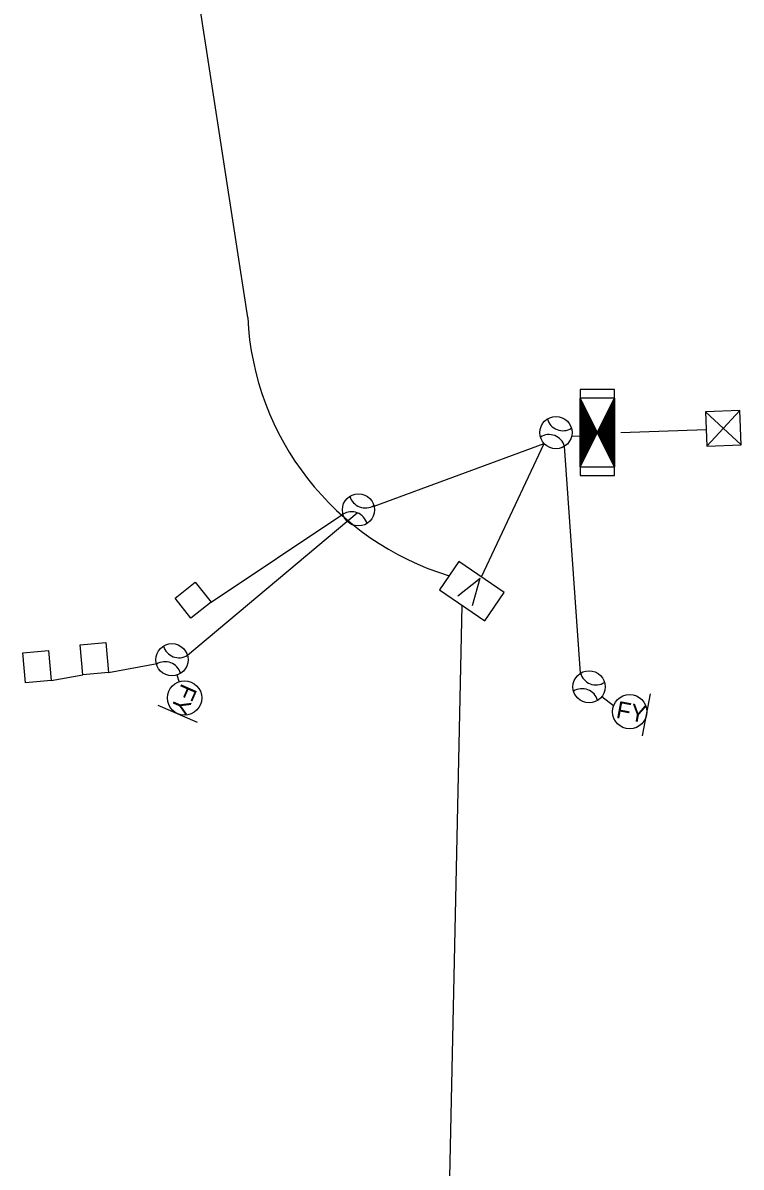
# Model space of a CAD drawing. Extents: x 601562 to 605316, y 332050 to 402250.
# Drawn here: x 604324.3 to 604491.7, y 339332.4 to 339598.9 of the extents above; entities that cross this region are included whole.
import ezdxf

# ---------------------------------------------------------------- set-up
doc = ezdxf.new("R2010")
doc.units = 0
doc.layers.add('P_FTMS', color=7, linetype='Continuous')
doc.layers.add('P_FTMSConduit', color=7, linetype='Continuous')

# ---------------------------------------------------------------- blocks, each defined once
blk = doc.blocks.new('FTMS_FCV')
at = {"layer": 'P_FTMS'}
blk.add_line((12.7, 16.3), (0.6, -21.9), dxfattribs=at)
blk.add_lwpolyline([(39.1, 24.4), (-39.1, 24.4), (-39.1, -24.4), (39.1, -24.4)], close=True, dxfattribs=at)
blk.add_lwpolyline([(-12.1, 16.2), (0.6, -21.9)], dxfattribs=at)
blk = doc.blocks.new('FTMS_FCB')
at = {"layer": 'P_FTMS'}
for p, q in [((-48.3, 24.1), (-48, 24.4)), ((-45.5, 22.7), (-47.1, 24.4)), ((-46.9, 23.4), (-46, 24.4)), ((-45.5, 22.8), (-43.9, 24.4)), ((-41.4, 20.7), (-45.1, 24.4)), ((-44.1, 22.1), (-41.8, 24.4)), ((-37.2, 18.6), (-43, 24.4)), ((-42.8, 21.4), (-39.8, 24.4)), ((-41.4, 20.7), (-37.7, 24.4)), ((-33.1, 16.5), (-40.9, 24.4)), ((-40, 20), (-35.6, 24.4)), ((-29, 14.5), (-38.9, 24.4)), ((-38.6, 19.3), (-33.6, 24.4)), ((-37.2, 18.6), (-31.5, 24.4)), ((-24.8, 12.4), (-36.8, 24.4)), ((-35.9, 17.9), (-29.4, 24.4)), ((-20.7, 10.3), (-34.7, 24.4)), ((-34.5, 17.2), (-27.3, 24.4)), ((-33.1, 16.5), (-25.3, 24.4)), ((-16.5, 8.3), (-32.7, 24.4)), ((-31.7, 15.9), (-23.2, 24.4)), ((-12.4, 6.2), (-30.6, 24.4)), ((-30.3, 15.2), (-21.1, 24.4)), ((-29, 14.5), (-19.1, 24.4)), ((-8.3, 4.1), (-28.5, 24.4)), ((-27.6, 13.8), (-17, 24.4)), ((-4.1, 2.1), (-26.4, 24.4)), ((-26.2, 13.1), (-14.9, 24.4)), ((-24.8, 12.4), (-12.9, 24.4)), ((0, 0), (-24.4, 24.4)), ((-23.5, 11.7), (-10.8, 24.4)), ((1.4, 0.7), (-22.3, 24.4)), ((-22.1, 11), (-8.7, 24.4)), ((-20.7, 10.3), (-6.7, 24.4)), ((2.8, 1.4), (-20.2, 24.4)), ((-19.3, 9.7), (-4.6, 24.4)), ((4.1, 2.1), (-18.2, 24.4)), ((-17.9, 9), (-2.5, 24.4)), ((-16.6, 8.3), (-0.4, 24.4)), ((5.5, 2.8), (-16.1, 24.4)), ((-15.2, 7.6), (1.6, 24.4)), ((6.9, 3.4), (-14, 24.4)), ((-13.8, 6.9), (3.7, 24.4)), ((-12.4, 6.2), (5.8, 24.4)), ((8.3, 4.1), (-12, 24.4)), ((-11, 5.5), (7.8, 24.4)), ((9.7, 4.8), (-9.9, 24.4)), ((-9.7, 4.8), (9.9, 24.4)), ((-8.3, 4.1), (12, 24.4)), ((11, 5.5), (-7.8, 24.4)), ((-6.9, 3.4), (14, 24.4)), ((12.4, 6.2), (-5.8, 24.4)), ((-5.5, 2.8), (16.1, 24.4)), ((-4.1, 2.1), (18.2, 24.4)), ((13.8, 6.9), (-3.7, 24.4)), ((-2.8, 1.4), (20.2, 24.4)), ((15.2, 7.6), (-1.6, 24.4)), ((-1.4, 0.7), (22.3, 24.4)), ((0, 0), (24.4, 24.4)), ((16.6, 8.3), (0.4, 24.4)), ((17.9, 9), (2.5, 24.4)), ((4.1, 2.1), (26.5, 24.4)), ((19.3, 9.7), (4.6, 24.4)), ((20.7, 10.3), (6.7, 24.4)), ((8.3, 4.1), (28.5, 24.4)), ((22.1, 11), (8.7, 24.4)), ((23.4, 11.7), (10.8, 24.4)), ((12.4, 6.2), (30.6, 24.4)), ((24.8, 12.4), (12.9, 24.4)), ((26.2, 13.1), (14.9, 24.4)), ((16.6, 8.3), (32.7, 24.4)), ((27.6, 13.8), (17, 24.4)), ((29, 14.5), (19.1, 24.4)), ((20.7, 10.3), (34.7, 24.4)), ((30.3, 15.2), (21.1, 24.4)), ((31.7, 15.9), (23.2, 24.4)), ((24.8, 12.4), (36.8, 24.4)), ((33.1, 16.6), (25.3, 24.4)), ((34.5, 17.2), (27.3, 24.4)), ((29, 14.5), (38.9, 24.4)), ((35.9, 17.9), (29.4, 24.4)), ((37.2, 18.6), (31.5, 24.4)), ((33.1, 16.6), (40.9, 24.4)), ((38.6, 19.3), (33.5, 24.4)), ((40, 20), (35.6, 24.4)), ((37.2, 18.6), (43, 24.4)), ((41.4, 20.7), (37.7, 24.4)), ((42.8, 21.4), (39.8, 24.4)), ((41.4, 20.7), (45.1, 24.4)), ((44.1, 22.1), (41.8, 24.4)), ((45.5, 22.8), (43.9, 24.4)), ((45.5, 22.8), (47.1, 24.4)), ((46.9, 23.5), (46, 24.4)), ((48.3, 24.1), (48, 24.4)), ((-24.4, -24.4), (0, 0)), ((24.4, -24.4), (0, 0)), ((-38.9, -24.4), (-29, -14.5)), ((-36.8, -24.4), (-24.8, -12.4)), ((-34.8, -24.4), (-20.7, -10.4)), ((-32.7, -24.4), (-16.6, -8.3)), ((-23.2, -24.4), (-31.7, -15.9)), ((-30.6, -24.4), (-12.4, -6.2)), ((-21.1, -24.4), (-30.3, -15.2)), ((-19, -24.4), (-29, -14.5)), ((-28.5, -24.4), (-8.3, -4.1)), ((-17, -24.4), (-27.6, -13.8)), ((-26.5, -24.4), (-4.1, -2.1)), ((-14.9, -24.4), (-26.2, -13.1)), ((-12.8, -24.4), (-24.8, -12.4)), ((-10.8, -24.4), (-23.4, -11.7)), ((-22.3, -24.4), (1.4, -0.7)), ((-8.7, -24.4), (-22.1, -11)), ((-6.6, -24.4), (-20.7, -10.3)), ((-20.3, -24.4), (2.8, -1.4)), ((-4.6, -24.4), (-19.3, -9.7)), ((-18.2, -24.4), (4.1, -2.1)), ((-2.5, -24.4), (-17.9, -9)), ((-0.4, -24.4), (-16.6, -8.3)), ((-16.1, -24.4), (5.5, -2.8)), ((1.6, -24.4), (-15.2, -7.6)), ((-14.1, -24.4), (6.9, -3.4)), ((3.7, -24.4), (-13.8, -6.9)), ((5.8, -24.4), (-12.4, -6.2)), ((-12, -24.4), (8.3, -4.1)), ((7.8, -24.4), (-11, -5.5)), ((-9.9, -24.4), (9.7, -4.8)), ((9.9, -24.4), (-9.7, -4.8)), ((12, -24.4), (-8.3, -4.1)), ((-7.8, -24.4), (11, -5.5)), ((14.1, -24.4), (-6.9, -3.5)), ((-5.8, -24.4), (12.4, -6.2)), ((16.1, -24.4), (-5.5, -2.8)), ((18.2, -24.4), (-4.1, -2.1)), ((-3.7, -24.4), (13.8, -6.9)), ((20.3, -24.4), (-2.8, -1.4)), ((-1.6, -24.4), (15.2, -7.6)), ((22.3, -24.4), (-1.4, -0.7)), ((0.4, -24.4), (16.6, -8.3)), ((2.5, -24.4), (17.9, -9)), ((26.5, -24.4), (4.1, -2.1)), ((4.6, -24.4), (19.3, -9.7)), ((6.6, -24.4), (20.7, -10.3)), ((28.5, -24.4), (8.3, -4.1)), ((8.7, -24.4), (22.1, -11)), ((10.8, -24.4), (23.4, -11.7)), ((30.6, -24.4), (12.4, -6.2)), ((12.8, -24.4), (24.8, -12.4)), ((14.9, -24.4), (26.2, -13.1)), ((32.7, -24.4), (16.6, -8.3)), ((17, -24.4), (27.6, -13.8)), ((19.1, -24.4), (29, -14.5)), ((34.7, -24.4), (20.7, -10.3)), ((21.1, -24.4), (30.3, -15.2)), ((23.2, -24.4), (31.7, -15.9)), ((36.8, -24.4), (24.8, -12.4)), ((38.9, -24.4), (29, -14.5)), ((-48, -24.4), (-48.3, -24.1)), ((-47.2, -24.4), (-45.5, -22.8)), ((-45.9, -24.4), (-46.9, -23.5)), ((-43.9, -24.4), (-45.5, -22.8)), ((-45.1, -24.4), (-41.4, -20.7)), ((-41.8, -24.4), (-44.1, -22.1)), ((-43, -24.4), (-37.3, -18.6)), ((-39.7, -24.4), (-42.8, -21.4)), ((-37.7, -24.4), (-41.4, -20.7)), ((-41, -24.4), (-33.1, -16.6)), ((-35.6, -24.4), (-40, -20)), ((-33.5, -24.4), (-38.6, -19.3)), ((-31.5, -24.4), (-37.2, -18.6)), ((-29.4, -24.4), (-35.9, -17.9)), ((-27.3, -24.4), (-34.5, -17.2)), ((-25.3, -24.4), (-33.1, -16.6)), ((25.3, -24.4), (33.1, -16.6)), ((27.3, -24.4), (34.5, -17.2)), ((29.4, -24.4), (35.9, -17.9)), ((31.5, -24.4), (37.2, -18.6)), ((40.9, -24.4), (33.1, -16.6)), ((33.5, -24.4), (38.6, -19.3)), ((35.6, -24.4), (40, -20)), ((43, -24.4), (37.2, -18.6)), ((37.7, -24.4), (41.4, -20.7)), ((39.7, -24.4), (42.8, -21.4)), ((45.1, -24.4), (41.4, -20.7)), ((41.8, -24.4), (44.1, -22.1)), ((43.9, -24.4), (45.5, -22.8)), ((47.2, -24.4), (45.5, -22.8)), ((46, -24.4), (46.9, -23.5)), ((48, -24.4), (48.3, -24.1))]:
    blk.add_line(p, q, dxfattribs=at)
for points in [[(61, 24.4), (-61, 24.4), (-61, -24.4), (61, -24.4)], [(48.8, 24.4), (-48.8, 24.4), (-48.8, -24.4), (48.8, -24.4)], [(48.8, 24.4), (0, 0), (-48.8, 24.4)], [(48.8, -24.4), (-48.8, -24.4), (0, 0)]]:
    blk.add_lwpolyline(points, close=True, dxfattribs=at)
blk = doc.blocks.new('FMB_1')
at = {"layer": 'P_FTMS'}
for p, q in [((24.4, -24.4), (-24.4, 24.4)), ((-24.4, -24.4), (24.4, 24.4))]:
    blk.add_line(p, q, dxfattribs=at)
blk.add_lwpolyline([(24.4, -24.4), (24.4, 24.4), (-24.4, 24.4), (-24.4, -24.4)], close=True, dxfattribs=at)
blk = doc.blocks.new('FFY')
at = {"layer": 'P_FTMS'}
blk.add_line((24.4, -30.5), (24.4, 30.5), dxfattribs=at)
blk.add_circle((0, 0), 24.4, dxfattribs=at)
blk.add_text('FY', height=24.38, dxfattribs=at).set_placement((-18.5, -12.2))

msp = doc.modelspace()

# ---------------------------------------------------------------- linework, layer by layer
at = {"layer": 'P_FTMS'}
for p, q in [((604368.18, 339464), (604398.89, 339484.48)), ((604344.21, 339447.63), (604355.62, 339449.69)), ((604330.86, 339445.77), (604338.23, 339447.12))]:
    msp.add_line(p, q, dxfattribs=at)
for points in [[(604368.18, 339464), (604363.47, 339460.27), (604359.75, 339464.97), (604364.45, 339468.7), (604368.18, 339464)], [(604343.61, 339454.6), (604344.21, 339447.63), (604344.21, 339447.63), (604338.23, 339447.12), (604337.64, 339454.09), (604343.61, 339454.6)], [(604330.26, 339452.74), (604330.86, 339445.77), (604330.86, 339445.76), (604324.88, 339445.25), (604324.28, 339452.23), (604330.26, 339452.74)]]:
    msp.add_lwpolyline(points, dxfattribs=at)
for centre in [(604448.54, 339503.49), (604402.5, 339485.5), (604359.04, 339450.6), (604456.25, 339444.3)]:
    msp.add_circle(centre, 3.75, dxfattribs=at)
for centre, start, end in [((604450.15, 339507.69), 195.8642, 302.1199), ((604446.92, 339499.29), 15.8642, 122.1199), ((604404.11, 339489.7), 195.8642, 302.1199), ((604400.89, 339481.3), 15.8642, 122.1199), ((604360.65, 339454.81), 195.8642, 302.1199), ((604357.43, 339446.4), 15.8642, 122.1199), ((604457.86, 339448.5), 195.8642, 302.1199), ((604454.64, 339440.1), 15.8642, 122.1199)]:
    msp.add_arc(centre, 3.75, start, end, dxfattribs=at)
at = {"layer": 'P_FTMSConduit'}
for p, q in [((604349.37, 339706.84), (604376.68, 339530.28)), ((604452.21, 339502.74), (604454.26, 339502.69)), ((604483.57, 339504.14), (604463.64, 339503.44)), ((604406.15, 339486.37), (604445.78, 339500.95)), ((604431.18, 339469.87), (604445.78, 339500.95)), ((604454.26, 339447.48), (604450.53, 339500.32)), ((604362.65, 339451.63), (604402.23, 339484.8)), ((604421.93, 339245.67), (604426.69, 339463.24)), ((604360.72, 339445.5), (604360.21, 339447.04)), ((604461.96, 339439.87), (604459.21, 339442))]:
    msp.add_line(p, q, dxfattribs=at)
msp.add_arc((604442.9, 339533.59), 66.3, 182.8594, 253.0948, dxfattribs=at)

# ---------------------------------------------------------------- block references
at = {"layer": 'P_FTMS'}
for name, p, xscale, yscale, rotation in [('FTMS_FCB', (604458.16, 339503.53), 0.16404166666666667, 0.16404166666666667, 90), ('FMB_1', (604487.56, 339504.48), 0.1640416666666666, 0.1640416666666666, 2.0261637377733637), ('FTMS_FCV', (604428.93, 339466.56), 0.16404166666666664, 0.1640416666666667, 145.88129352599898), ('FFY', (604361.96, 339441.7), 0.16404166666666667, 0.1640416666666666, -113.67424300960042), ('FFY', (604465.72, 339438.5), 0.16404166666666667, 0.16404166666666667, -10.610601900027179)]:
    msp.add_blockref(name, p, dxfattribs=dict(at, xscale=xscale, yscale=yscale, rotation=rotation))

doc.saveas('drawing.dxf')
